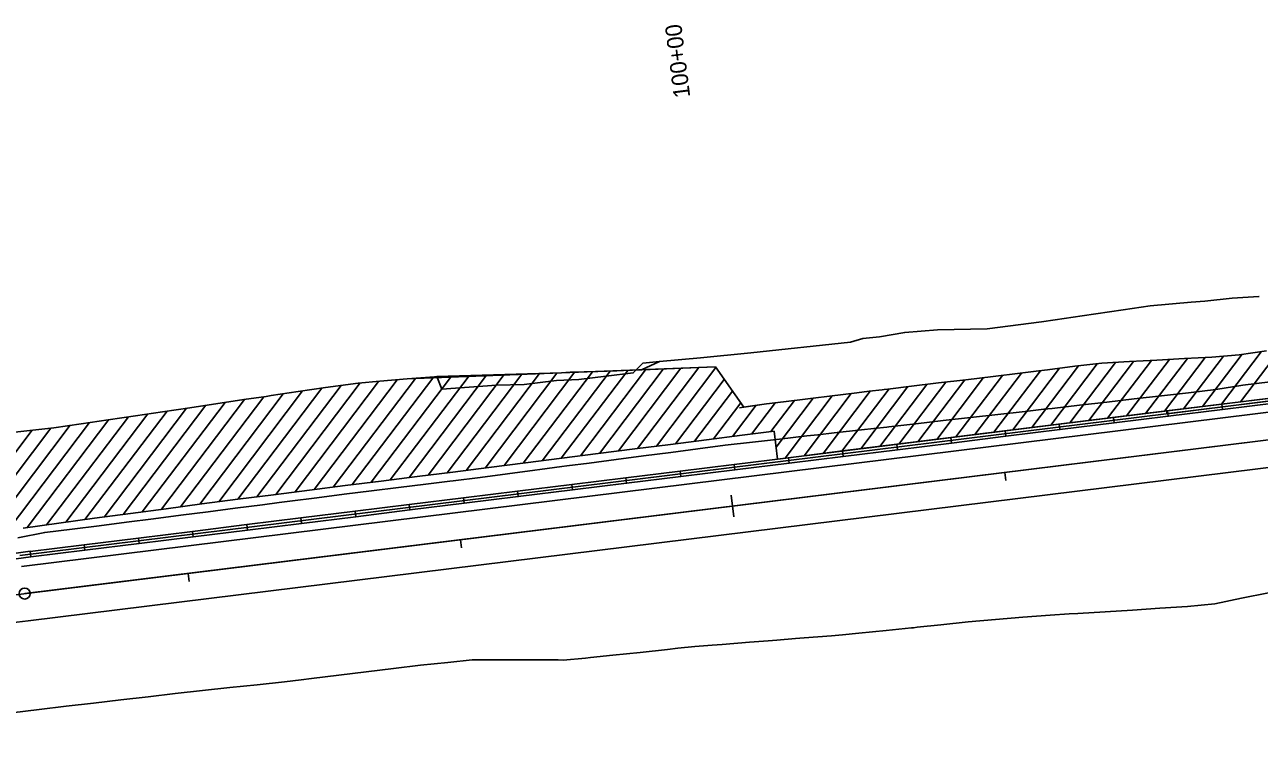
# Model space of a CAD drawing. Extents: x 1568809 to 1572786, y 728326 to 734907.
# Drawn here: x 1570028.4 to 1570478.4, y 732096.1 to 732357.8 of the extents above; entities that cross this region are included whole.
import ezdxf

# ---------------------------------------------------------------- set-up
doc = ezdxf.new("R2010")
doc.units = 0
for name, color, linetype in [('R_Horz Alg', 7, 'Continuous'), ('R_Horz Alg Annot', 7, 'Continuous'), ('R_MOT', 7, 'Continuous'), ('R_No Plot', 7, 'Continuous'), ('R_Striping', 7, 'Continuous')]:
    doc.layers.add(name, color=color, linetype=linetype)

msp = doc.modelspace()

# ---------------------------------------------------------------- linework, layer by layer
at = {"layer": 'R_Horz Alg'}
msp.add_line((1569774.69, 732119.01), (1571082.41, 732280.73), dxfattribs=at)
at = {"layer": 'R_Horz Alg Annot'}
for points in [[(1570386.01, 732191.59), (1570385.64, 732194.56)], [(1570285.91, 732186.26), (1570286.89, 732178.32)], [(1570187.52, 732167.04), (1570187.15, 732170.02)], [(1570088.28, 732154.77), (1570087.91, 732157.74)]]:
    msp.add_lwpolyline(points, dxfattribs=at)
msp.add_circle((1570028.36, 732150.38), 2, dxfattribs=at)
at = {"layer": 'R_MOT'}
for p, q in [((1570423.08, 732214.31), (1570439.03, 732235.39)), ((1570430, 732215.16), (1570445.58, 732235.76)), ((1570436.92, 732216.02), (1570452.13, 732236.13)), ((1570443.83, 732216.87), (1570458.67, 732236.49)), ((1570450.75, 732217.73), (1570465.32, 732236.99)), ((1570457.67, 732218.59), (1570472.07, 732237.62)), ((1570464.58, 732219.44), (1570479.07, 732238.58)), ((1570471.5, 732220.3), (1570486.06, 732239.55)), ((1570582.65, 732233.03), (1570026.64, 732164.27)), ((1570196.18, 732196.15), (1570222.37, 732230.76)), ((1570203.12, 732197.03), (1570228.94, 732231.17)), ((1570210.06, 732197.92), (1570235.3, 732231.28)), ((1570217, 732198.81), (1570241.74, 732231.51)), ((1570223.95, 732199.7), (1570248.21, 732231.77)), ((1570230.89, 732200.59), (1570254.65, 732232)), ((1570237.83, 732201.48), (1570261.11, 732232.25)), ((1570244.77, 732202.37), (1570267.57, 732232.51)), ((1570251.72, 732203.26), (1570274.03, 732232.76)), ((1570258.65, 732204.14), (1570280.3, 732232.75)), ((1570374.67, 732208.32), (1570391.65, 732230.77)), ((1570381.58, 732209.18), (1570398.55, 732231.6)), ((1570388.5, 732210.03), (1570405.53, 732232.55)), ((1570395.42, 732210.89), (1570412.49, 732233.45)), ((1570402.33, 732211.74), (1570419.31, 732234.18)), ((1570409.25, 732212.6), (1570425.93, 732234.65)), ((1570416.17, 732213.45), (1570432.48, 732235.02)), ((1570113.01, 732185.66), (1570143.73, 732226.26)), ((1570119.95, 732186.55), (1570150.69, 732227.17)), ((1570126.9, 732187.44), (1570157.38, 732227.74)), ((1570133.84, 732188.33), (1570164.08, 732228.3)), ((1570140.78, 732189.21), (1570170.77, 732228.85)), ((1570147.72, 732190.1), (1570177.44, 732229.38)), ((1570154.64, 732190.96), (1570183.9, 732229.63)), ((1570161.56, 732191.82), (1570190.31, 732229.82)), ((1570168.49, 732192.69), (1570196.72, 732230.01)), ((1570175.41, 732193.55), (1570203.13, 732230.2)), ((1570182.33, 732194.42), (1570209.54, 732230.38)), ((1570189.26, 732195.28), (1570215.95, 732230.57)), ((1570265.59, 732205.02), (1570283.32, 732228.46)), ((1570340.09, 732204.04), (1570357.19, 732226.65)), ((1570347, 732204.9), (1570364.08, 732227.47)), ((1570353.92, 732205.75), (1570370.97, 732228.3)), ((1570360.83, 732206.61), (1570377.86, 732229.12)), ((1570367.75, 732207.47), (1570384.76, 732229.94)), ((1570085.2, 732182.04), (1570115.54, 732222.15)), ((1570092.18, 732182.98), (1570122.6, 732223.19)), ((1570099.13, 732183.88), (1570129.66, 732224.24)), ((1570106.07, 732184.77), (1570136.71, 732225.28)), ((1570272.52, 732205.9), (1570286.34, 732224.16)), ((1570302.23, 732203.74), (1570315.79, 732221.66)), ((1570305.5, 732199.77), (1570322.69, 732222.49)), ((1570312.42, 732200.62), (1570329.59, 732223.32)), ((1570319.34, 732201.48), (1570336.49, 732224.16)), ((1570326.25, 732202.33), (1570343.39, 732224.99)), ((1570333.17, 732203.19), (1570350.29, 732225.83)), ((1570057.27, 732178.27), (1570087.31, 732217.98)), ((1570064.25, 732179.21), (1570094.37, 732219.03)), ((1570071.23, 732180.16), (1570101.43, 732220.07)), ((1570078.22, 732181.1), (1570108.48, 732221.11)), ((1570279.46, 732206.78), (1570289.36, 732219.87)), ((1570286.39, 732207.65), (1570294.99, 732219.03)), ((1570293.33, 732208.53), (1570301.99, 732219.99)), ((1570300.26, 732209.41), (1570308.89, 732220.82)), ((1570022.29, 732173.47), (1570052.02, 732212.78)), ((1570029.3, 732174.44), (1570059.08, 732213.82)), ((1570036.3, 732175.42), (1570066.14, 732214.86)), ((1570043.3, 732176.39), (1570073.2, 732215.9)), ((1570050.29, 732177.33), (1570080.25, 732216.94)), ((1570001.26, 732170.54), (1570031.04, 732209.91)), ((1570008.27, 732171.51), (1570037.93, 732210.73)), ((1570015.28, 732172.49), (1570044.97, 732211.73))]:
    msp.add_line(p, q, dxfattribs=at)
for points in [[(1570464.68, 732219.45), (1570484.42, 732221.89), (1570484.66, 732219.91), (1570464.92, 732217.47)], [(1570444.93, 732217.01), (1570464.68, 732219.45), (1570464.92, 732217.47), (1570445.18, 732215.03)], [(1570405.45, 732212.12), (1570425.19, 732214.56), (1570425.43, 732212.59), (1570405.69, 732210.15)], [(1570425.19, 732214.56), (1570444.93, 732217.01), (1570445.18, 732215.03), (1570425.43, 732212.59)], [(1570365.96, 732207.24), (1570385.7, 732209.68), (1570385.95, 732207.71), (1570366.21, 732205.26)], [(1570385.7, 732209.68), (1570405.45, 732212.12), (1570405.69, 732210.15), (1570385.95, 732207.71)], [(1570326.47, 732202.36), (1570346.22, 732204.8), (1570346.46, 732202.82), (1570326.72, 732200.38)], [(1570346.22, 732204.8), (1570365.96, 732207.24), (1570366.21, 732205.26), (1570346.46, 732202.82)], [(1570286.99, 732197.47), (1570306.73, 732199.91), (1570306.98, 732197.94), (1570287.23, 732195.5)], [(1570306.73, 732199.91), (1570326.47, 732202.36), (1570326.72, 732200.38), (1570306.98, 732197.94)], [(1570247.5, 732192.59), (1570267.25, 732195.03), (1570267.49, 732193.06), (1570247.75, 732190.61)], [(1570267.25, 732195.03), (1570286.99, 732197.47), (1570287.23, 732195.5), (1570267.49, 732193.06)], [(1570227.76, 732190.15), (1570247.5, 732192.59), (1570247.75, 732190.61), (1570228, 732188.17)], [(1570188.27, 732185.26), (1570208.02, 732187.71), (1570208.26, 732185.73), (1570188.52, 732183.29)], [(1570208.02, 732187.71), (1570227.76, 732190.15), (1570228, 732188.17), (1570208.26, 732185.73)], [(1570148.79, 732180.38), (1570168.53, 732182.82), (1570168.77, 732180.85), (1570149.03, 732178.41)], [(1570168.53, 732182.82), (1570188.27, 732185.26), (1570188.52, 732183.29), (1570168.77, 732180.85)], [(1570109.3, 732175.5), (1570129.04, 732177.94), (1570129.29, 732175.96), (1570109.54, 732173.52)], [(1570129.04, 732177.94), (1570148.79, 732180.38), (1570149.03, 732178.41), (1570129.29, 732175.96)], [(1570069.81, 732170.61), (1570089.56, 732173.06), (1570089.8, 732171.08), (1570070.06, 732168.64)], [(1570089.56, 732173.06), (1570109.3, 732175.5), (1570109.54, 732173.52), (1570089.8, 732171.08)], [(1570030.33, 732165.73), (1570050.07, 732168.17), (1570050.31, 732166.2), (1570030.57, 732163.76)], [(1570050.07, 732168.17), (1570069.81, 732170.61), (1570070.06, 732168.64), (1570050.31, 732166.2)], [(1570010.6, 732163.02), (1570030.3, 732165.79), (1570030.58, 732163.82), (1570010.88, 732161.05)]]:
    msp.add_lwpolyline(points, close=True, dxfattribs=at)
at = {"layer": 'R_No Plot'}
for p, q in [((1570444.57, 732216.97), (1570896.54, 732272.86)), ((1570444.57, 732216.97), (1570896.54, 732272.86)), ((1570444.57, 732216.97), (1570896.54, 732272.86)), ((1570582.65, 732233.03), (1570026.64, 732164.27)), ((1570280.13, 732233), (1570290.43, 732218.36)), ((1570290.43, 732218.36), (1570280.13, 732233)), ((1570149.86, 732227.11), (1570137.98, 732225.46)), ((1570149.86, 732227.11), (1570137.98, 732225.46)), ((1570149.86, 732227.11), (1570137.98, 732225.46)), ((1570108.29, 732221.08), (1570088.5, 732218.16)), ((1570108.29, 732221.08), (1570088.5, 732218.16)), ((1570108.29, 732221.08), (1570088.5, 732218.16)), ((1570302.77, 732199.43), (1570301.51, 732209.57)), ((1570302.77, 732199.43), (1570301.51, 732209.57))]:
    msp.add_line(p, q, dxfattribs=at)
for points in [[(1571080.52, 732296.05), (1570973.02, 732293.44), (1570943.63, 732289.39), (1570933.75, 732279.73), (1570896.54, 732272.86), (1570444.72, 732215.92), (1570444.57, 732216.97), (1570302.77, 732199.43)], [(1571080.52, 732296.05), (1570973.02, 732293.44), (1570943.63, 732289.39), (1570933.75, 732279.73), (1570896.54, 732272.86), (1570444.72, 732215.92), (1570444.57, 732216.97), (1570302.77, 732199.43)], [(1570478.23, 732258.71), (1570468.47, 732258.11), (1570458.53, 732257.03), (1570453.54, 732256.61), (1570438.59, 732255.3), (1570428.69, 732253.87), (1570423.74, 732253.14), (1570413.84, 732251.69), (1570403.95, 732250.24), (1570399, 732249.51), (1570379.16, 732246.94), (1570361.04, 732246.5), (1570349.1, 732245.6), (1570339.9, 732244.05), (1570333.83, 732243.44)], [(1570478.23, 732258.71), (1570468.47, 732258.11), (1570458.53, 732257.03), (1570453.54, 732256.61), (1570438.59, 732255.3), (1570428.69, 732253.87), (1570423.74, 732253.14), (1570413.84, 732251.69), (1570403.95, 732250.24), (1570399, 732249.51), (1570379.16, 732246.94), (1570361.04, 732246.5), (1570349.1, 732245.6), (1570339.9, 732244.05), (1570333.83, 732243.44)], [(1570333.83, 732243.44), (1570329.39, 732242.01), (1570293.02, 732238.13), (1570274.67, 732236.36), (1570259.73, 732234.95), (1570253.61, 732234.37), (1570250.16, 732230.84), (1570240.24, 732229.64), (1570230.32, 732228.38), (1570222.15, 732228.02), (1570216.27, 732227.31), (1570210.38, 732226.6), (1570200.33, 732226.42), (1570180.37, 732224.86), (1570178.64, 732229.48), (1570177.79, 732229.41), (1570167.81, 732228.62), (1570157.84, 732227.78), (1570149.86, 732227.11)], [(1570333.83, 732243.44), (1570329.39, 732242.01), (1570293.02, 732238.13), (1570274.67, 732236.36), (1570259.73, 732234.95), (1570253.17, 732231.91), (1570246.66, 732231.73), (1570244.14, 732231.61), (1570237.22, 732231.31), (1570227.17, 732231.13), (1570223.97, 732230.81), (1570178.64, 732229.48), (1570177.79, 732229.41), (1570167.81, 732228.62), (1570157.84, 732227.78), (1570149.86, 732227.11)], [(1570288.87, 732218.14), (1570291.98, 732218.59), (1570298.76, 732219.57), (1570301.89, 732219.98), (1570311.82, 732221.18), (1570315.78, 732221.66), (1570321.74, 732222.38), (1570331.67, 732223.58), (1570336.22, 732224.13), (1570340.87, 732224.69), (1570341.6, 732224.78), (1570342.94, 732224.94), (1570351.53, 732225.98), (1570361.46, 732227.16), (1570371.39, 732228.35), (1570381.32, 732229.53), (1570391.25, 732230.72), (1570398.05, 732231.54), (1570401.17, 732231.95), (1570411.08, 732233.3), (1570421.02, 732234.37), (1570431.03, 732234.94), (1570441.03, 732235.5), (1570451.04, 732236.07), (1570461.05, 732236.62), (1570471.02, 732237.48), (1570480.93, 732238.84)], [(1570480.93, 732238.84), (1570471.02, 732237.48), (1570461.05, 732236.62), (1570451.04, 732236.07), (1570441.03, 732235.5), (1570431.03, 732234.94), (1570421.02, 732234.37), (1570411.08, 732233.3), (1570401.17, 732231.95), (1570398.05, 732231.54), (1570391.25, 732230.72), (1570381.32, 732229.53), (1570371.39, 732228.35), (1570361.46, 732227.16), (1570351.53, 732225.98), (1570342.94, 732224.94), (1570341.6, 732224.78), (1570340.87, 732224.69), (1570336.22, 732224.13), (1570331.67, 732223.58), (1570321.74, 732222.38), (1570315.78, 732221.66), (1570311.82, 732221.18), (1570301.89, 732219.98), (1570298.76, 732219.57), (1570290.43, 732218.36)], [(1570149.86, 732227.11), (1570157.84, 732227.78), (1570167.81, 732228.62), (1570280.13, 732233)], [(1570253.25, 732231.95), (1570253.17, 732231.91), (1570246.66, 732231.73), (1570244.14, 732231.61), (1570237.22, 732231.31), (1570227.17, 732231.13), (1570223.97, 732230.81), (1570178.64, 732229.48), (1570177.79, 732229.41), (1570167.81, 732228.62), (1570157.84, 732227.78), (1570149.86, 732227.11)], [(1570280.13, 732233), (1570253.25, 732231.95)], [(1570025.85, 732170.67), (1570035.69, 732172.64), (1570045.61, 732173.86), (1570055.53, 732175.11), (1570065.45, 732176.38), (1570075.37, 732177.64), (1570085.29, 732178.92), (1570095.21, 732180.22), (1570105.13, 732181.48), (1570115.05, 732182.74), (1570121.14, 732183.54), (1570124.96, 732184.05), (1570134.88, 732185.29), (1570144.8, 732186.57), (1570154.73, 732187.8), (1570164.65, 732189.03), (1570174.57, 732190.26), (1570183.36, 732191.36), (1570184.5, 732191.5), (1570194.42, 732192.73), (1570204.33, 732194.04), (1570214.25, 732195.35), (1570216.08, 732195.6), (1570224.16, 732196.65), (1570226, 732196.9), (1570234.08, 732197.96), (1570243.99, 732199.27), (1570253.91, 732200.56), (1570263.83, 732201.86), (1570273.74, 732203.15), (1570283.66, 732204.45), (1570293.59, 732205.59), (1570303.53, 732206.73), (1570313.47, 732207.83), (1570317.43, 732208.28), (1570323.41, 732208.94), (1570333.34, 732210.07), (1570337.9, 732210.58), (1570342.55, 732211.11), (1570343.28, 732211.19), (1570353.22, 732212.32), (1570363.15, 732213.44), (1570373.1, 732214.53), (1570383.03, 732215.66), (1570392.97, 732216.79), (1570399.78, 732217.56), (1570402.91, 732217.91), (1570412.84, 732219.08), (1570422.77, 732220.22), (1570432.71, 732221.35), (1570442.65, 732222.48), (1570452.58, 732223.59), (1570462.51, 732224.81), (1570472.39, 732226.37), (1570482.32, 732227.56)], [(1570137.98, 732225.46), (1570128.08, 732224), (1570118.18, 732222.54), (1570116.35, 732222.27), (1570108.29, 732221.08)], [(1570137.98, 732225.46), (1570128.08, 732224), (1570118.18, 732222.54), (1570116.35, 732222.27), (1570108.29, 732221.08)], [(1570137.98, 732225.46), (1570128.08, 732224), (1570118.18, 732222.54), (1570116.35, 732222.27), (1570108.29, 732221.08)], [(1570088.5, 732218.16), (1570078.6, 732216.7), (1570068.71, 732215.24), (1570058.81, 732213.78), (1570048.92, 732212.32), (1570039.02, 732210.86), (1570029.09, 732209.67), (1570019.15, 732208.56), (1570009.21, 732207.44), (1569999.28, 732206.32)], [(1570088.5, 732218.16), (1570078.6, 732216.7), (1570068.71, 732215.24), (1570058.81, 732213.78), (1570048.92, 732212.32), (1570039.02, 732210.86), (1570029.09, 732209.67), (1570019.15, 732208.56), (1570009.21, 732207.44), (1569999.28, 732206.32)], [(1570088.5, 732218.16), (1570078.6, 732216.7), (1570068.71, 732215.24), (1570058.81, 732213.78), (1570048.92, 732212.32), (1570039.02, 732210.86), (1570029.09, 732209.67), (1570019.15, 732208.56), (1570009.21, 732207.44), (1569999.28, 732206.32)], [(1570301.51, 732209.57), (1570302.77, 732199.43), (1570373.67, 732208.2), (1570444.57, 732216.97)], [(1570301.51, 732209.57), (1570302.77, 732199.43), (1570373.67, 732208.2), (1570444.57, 732216.97)], [(1570301.51, 732209.57), (1570302.77, 732199.43), (1570373.67, 732208.2), (1570444.57, 732216.97)], [(1570301.51, 732209.57), (1570289.87, 732208.1), (1570276.82, 732206.44), (1570263.78, 732204.79), (1570250.74, 732203.13), (1570237.44, 732201.43), (1570224.14, 732199.72), (1570210.85, 732198.02), (1570197.55, 732196.32), (1570184.46, 732194.68), (1570171.36, 732193.05), (1570158.27, 732191.41), (1570145.18, 732189.78), (1570132.12, 732188.11), (1570119.06, 732186.43), (1570106, 732184.76), (1570092.95, 732183.09), (1570079.91, 732181.33), (1570066.88, 732179.57), (1570053.85, 732177.81), (1570040.82, 732176.05), (1570027.86, 732174.24)], [(1570301.51, 732209.57), (1570289.87, 732208.1), (1570276.82, 732206.44), (1570263.78, 732204.79), (1570250.74, 732203.13), (1570237.44, 732201.43), (1570224.14, 732199.72), (1570210.85, 732198.02), (1570197.55, 732196.32), (1570184.46, 732194.68), (1570171.36, 732193.05), (1570158.27, 732191.41), (1570145.18, 732189.78), (1570132.12, 732188.11), (1570119.06, 732186.43), (1570106, 732184.76), (1570092.95, 732183.09), (1570079.91, 732181.33), (1570066.88, 732179.57), (1570053.85, 732177.81), (1570040.82, 732176.05), (1570027.86, 732174.24)], [(1570027.86, 732174.24), (1570040.82, 732176.05), (1570053.85, 732177.81), (1570066.88, 732179.57), (1570079.91, 732181.33), (1570092.95, 732183.09), (1570106, 732184.76), (1570119.06, 732186.43), (1570132.12, 732188.11), (1570145.18, 732189.78), (1570158.27, 732191.41), (1570171.36, 732193.05), (1570184.46, 732194.68), (1570197.55, 732196.32), (1570210.85, 732198.02), (1570224.14, 732199.72), (1570237.44, 732201.43), (1570250.74, 732203.13), (1570263.78, 732204.79), (1570276.82, 732206.44), (1570289.87, 732208.1), (1570301.51, 732209.57)], [(1570027.86, 732174.24), (1570040.82, 732176.05), (1570053.85, 732177.81), (1570066.88, 732179.57), (1570079.91, 732181.33), (1570092.95, 732183.09), (1570106, 732184.76), (1570119.06, 732186.43), (1570132.12, 732188.11), (1570145.18, 732189.78), (1570158.27, 732191.41), (1570171.36, 732193.05), (1570184.46, 732194.68), (1570197.55, 732196.32), (1570210.85, 732198.02), (1570224.14, 732199.72), (1570237.44, 732201.43), (1570250.74, 732203.13), (1570263.78, 732204.79), (1570276.82, 732206.44), (1570289.87, 732208.1), (1570301.51, 732209.57)], [(1570027.86, 732174.24), (1570040.82, 732176.05), (1570053.85, 732177.81), (1570066.88, 732179.57), (1570079.91, 732181.33), (1570092.95, 732183.09), (1570106, 732184.76), (1570119.06, 732186.43), (1570132.12, 732188.11), (1570145.18, 732189.78), (1570158.27, 732191.41), (1570171.36, 732193.05), (1570184.46, 732194.68), (1570197.55, 732196.32), (1570210.85, 732198.02), (1570224.14, 732199.72), (1570237.44, 732201.43), (1570250.74, 732203.13), (1570263.78, 732204.79), (1570276.82, 732206.44), (1570289.87, 732208.1), (1570301.51, 732209.57)], [(1570481.76, 732150.66), (1570471.92, 732148.74), (1570462.1, 732146.65), (1570452.15, 732145.61), (1570442.15, 732144.99), (1570432.16, 732144.3), (1570422.16, 732143.71), (1570412.16, 732143.12), (1570409, 732142.94), (1570402.16, 732142.48), (1570392.16, 732141.82), (1570382.2, 732140.92), (1570372.23, 732140.04), (1570362.29, 732138.98), (1570353.68, 732138.06), (1570352.34, 732137.91), (1570351.61, 732137.84), (1570346.95, 732137.34), (1570342.4, 732136.85), (1570332.44, 732135.91), (1570326.46, 732135.27), (1570322.48, 732134.94), (1570312.5, 732134.19), (1570309.36, 732133.93), (1570302.52, 732133.42), (1570299.37, 732133.18), (1570292.53, 732132.66), (1570282.57, 732131.78), (1570278.92, 732131.51), (1570272.58, 732131.05), (1570266.46, 732130.4), (1570262.64, 732129.99), (1570252.69, 732128.93), (1570242.74, 732127.95), (1570234.63, 732127.1), (1570232.8, 732126.85), (1570224.67, 732126.14), (1570222.8, 732126.18), (1570212.72, 732126.23), (1570202.64, 732126.24), (1570192.57, 732126.23), (1570191.41, 732126.23), (1570182.61, 732125.29), (1570172.66, 732124.21), (1570162.74, 732123.03), (1570152.81, 732121.8), (1570142.89, 732120.58), (1570132.96, 732119.35), (1570129.13, 732118.94), (1570123.03, 732118.18), (1570113.08, 732117.13), (1570103.14, 732116.06), (1570093.2, 732115), (1570083.26, 732113.89), (1570073.32, 732112.77), (1570063.38, 732111.62), (1570053.45, 732110.45), (1570043.52, 732109.27), (1570033.6, 732108.05), (1570023.67, 732106.82)]]:
    msp.add_lwpolyline(points, dxfattribs=at)
msp.add_arc((1570478.24, 732258.55), 0.16, 42.7401, 93.2038, dxfattribs=at)
msp.add_arc((1570478.24, 732258.55), 0.16, 42.7401, 93.2038, dxfattribs=at)
at = {"layer": 'R_Striping'}
for p, q in [((1570027.14, 732160.3), (1571081.18, 732290.66)), ((1570028.36, 732150.38), (1571082.41, 732280.73)), ((1570029.59, 732140.45), (1571083.64, 732270.81))]:
    msp.add_line(p, q, dxfattribs=at)
msp.add_arc((1570379.97, 729307.25), 2854.79, 97.05, 102.33591, dxfattribs=at)

# ---------------------------------------------------------------- texts
at = {"layer": 'R_Horz Alg Annot'}
msp.add_text('100+00', height=6, rotation=97.05, dxfattribs=at).set_placement((1570270.96, 732331.52))

doc.saveas('drawing.dxf')
